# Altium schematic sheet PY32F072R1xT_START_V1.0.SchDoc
size 381 x 254 mm; SheetNumber: 1; SheetTotal: 1
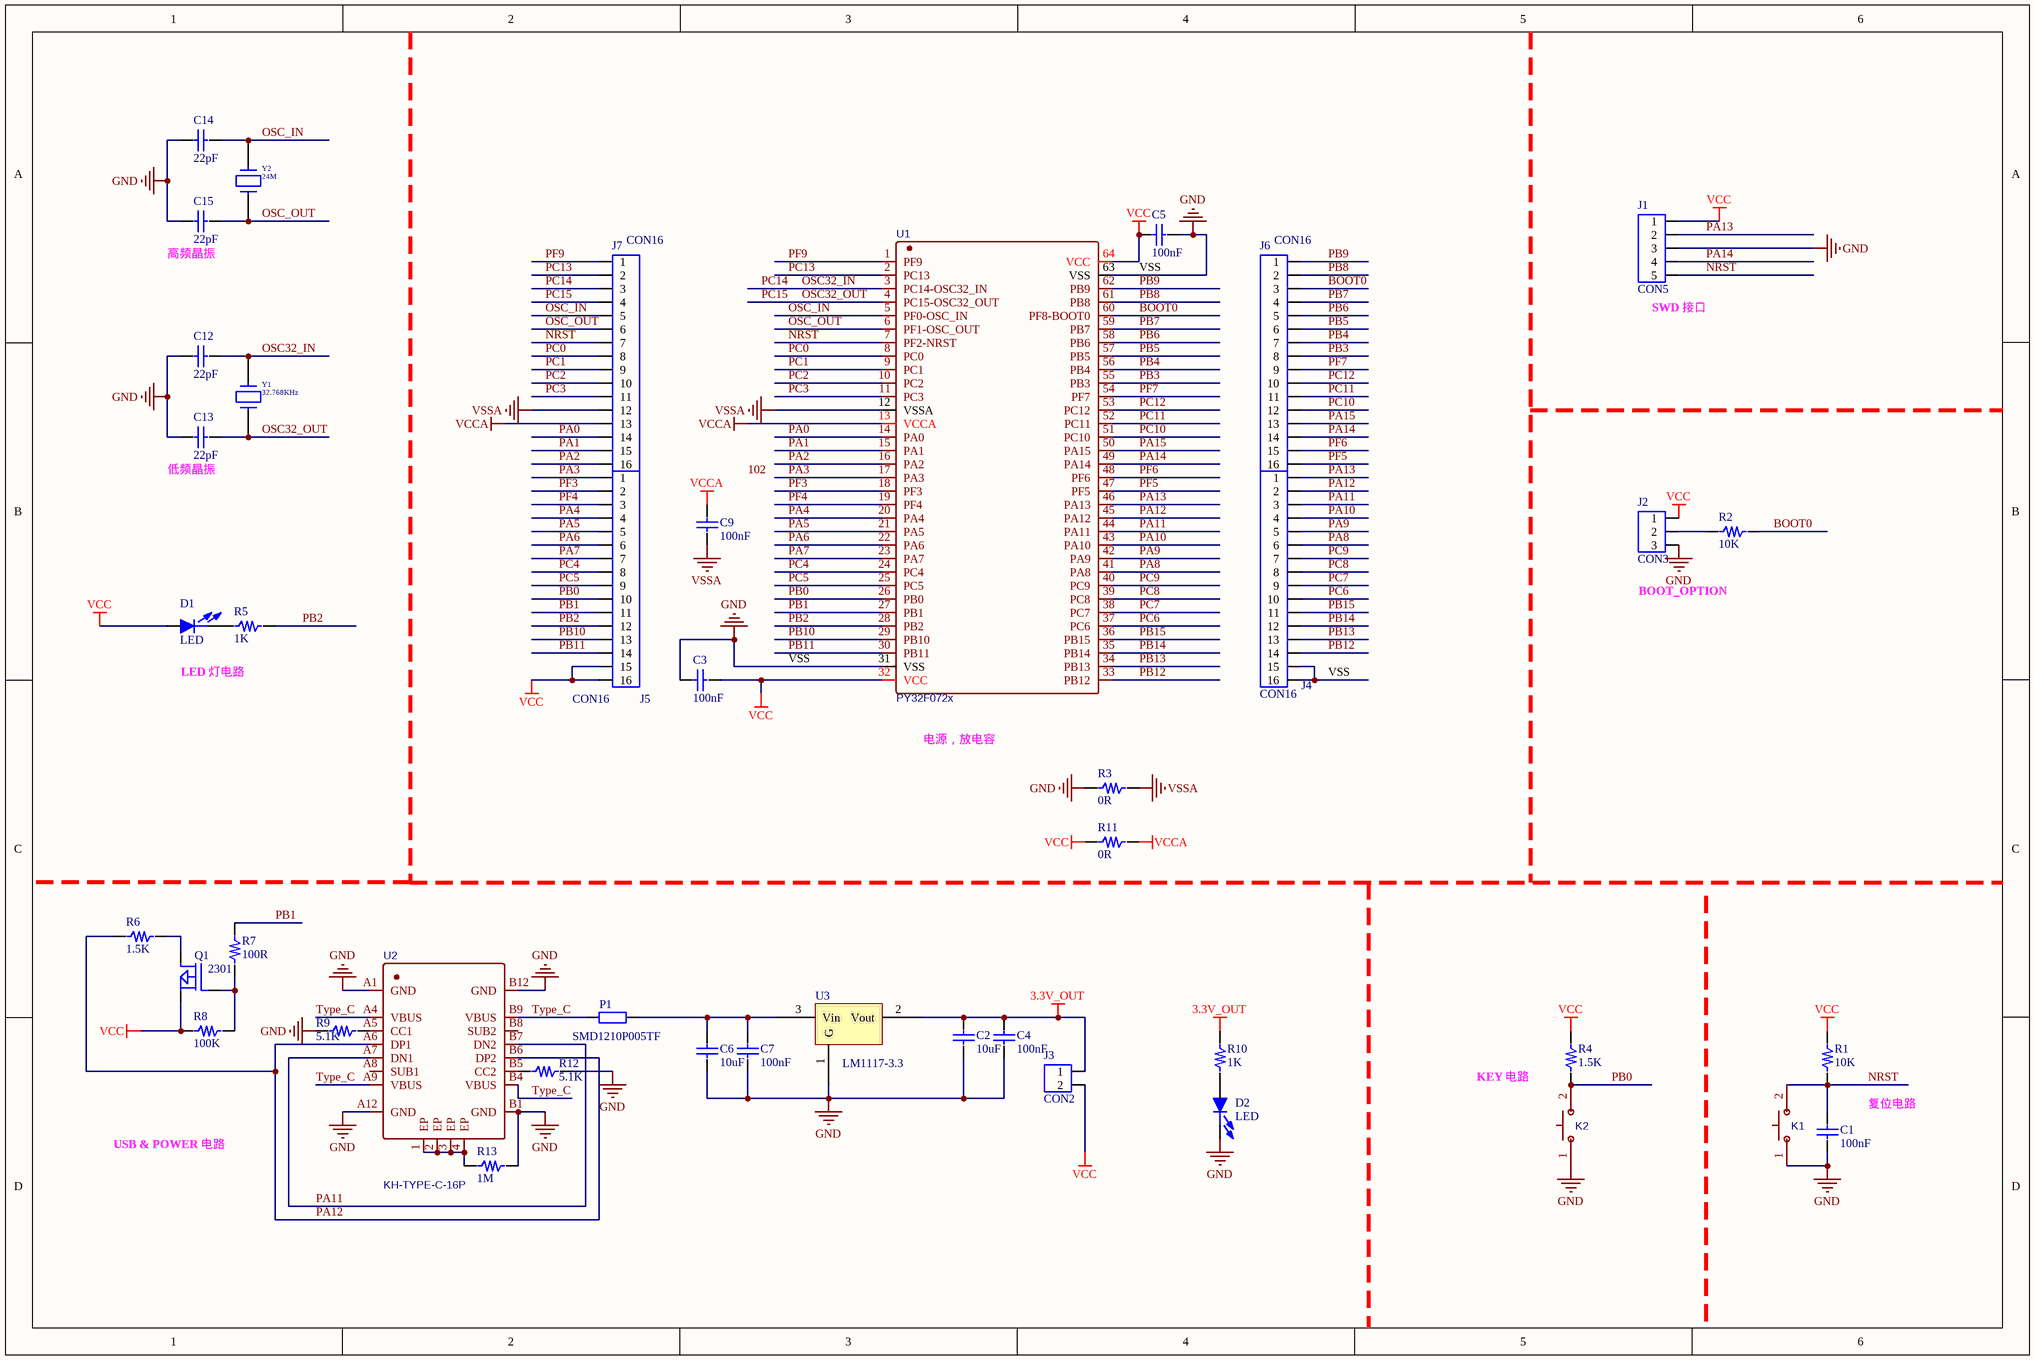
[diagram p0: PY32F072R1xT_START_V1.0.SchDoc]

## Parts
C1  100nF  [C0603]
C2  10uF  [C0805]
C3  100nF  [C0603]
C4  100nF  [C0603]
C5  100nF  [C0603]
C6  10uF  [C0805]
C7  100nF  [C0603]
C9  100nF  [C0603]
C12  22pF  [C0603]
C13  22pF  [C0603]
C14  22pF  [C0603]
C15  22pF  [C0603]
D1  LED  [LED-0805]
D2  LED  [LED-0805]
J1  CON5  [CON5]
J2  CON3  [CON3]
J3  CON2  [CON2]
J4  CON16  [CON16]
J5  CON16  [CON16]
J6  CON16  [CON16]
J7  CON16  [CON16]
K1  1TS002B-2600-5001_key  [SW]  (value not drawn)
K2  1TS002B-2600-5001_key  [SW]  (value not drawn)
P1  SMD1210P005TF  [SDM1210P005TF]
Q1  2301  [SOT23 2301]
R1  10K  [R0603]
R2  10K  [R0603]
R3  0R  [R0603]
R4  1.5K  [R0603]
R5  1K  [R0603]
R6  1.5K  [R0603]
R7  100R  [R0603]
R8  100K  [R0603]
R9  5.1K  [R0603]
R10  1K  [R0603]
R11  0R  [R0603]
R12  5.1K  [R0603]
R13  1M  [R0603]
U1  PY32F072x  [LQFP-64_L10.0-W10.0-P0.50-LS12.0-BL]
U2  KH-TYPE-C-16P  [USB-C-SMD_KH-TYPE-C-16P]
U3  LM1117-3.3  [LM1117-3.3]
Y1  32.768KHz  [32768KHZ_2]
Y2  24M  [25MHZ_2]

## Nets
3.3V_OUT: C2.2 C4.2 J3.1 R10.2 U3.2(Vout)
VCC: C3.2 C5.2 D1.2 J1.1 J2.1 J3.2 J5.15 J5.16 Q1.2(S) R1.2 R4.2 R8.1 R11.1 U1.32(VCC) U1.64(VCC)
VCCA: C9.2 J7.13 R11.2 U1.13(VCCA)
VSS: C1.1 C2.1 C3.1 C4.1 C5.1 C6.1 C7.1 C12.2 C13.2 C14.2 C15.2 D2.1 J1.3 J2.3 J4.15 J4.16 K1.1(A) K2.1(A) R3.1 R9.2 R12.1 R13.1 U1.31(VSS) U1.63(VSS) U2.A1(GND) U2.A12(GND) U2.B1(GND) U2.B12(GND) U3.1(G)  [also labelled GND]
VSSA: C9.1 J7.12 R3.2 U1.12(VSSA)
BOOT0: J6.3 R2.2 U1.60(PF8-BOOT0)
NRST: C1.2 J1.5 J7.7 K1.2(B) R1.1 U1.7(PF2-NRST)
OSC32_IN: C12.1 J7.3 U1.3(PC14-OSC32_IN) Y1.1  [also labelled PC14]
OSC32_OUT: C13.1 J7.4 U1.4(PC15-OSC32_OUT) Y1.2  [also labelled PC15]
OSC_IN: C14.1 J7.5 U1.5(PF0-OSC_IN) Y2.2
OSC_OUT: C15.1 J7.6 U1.6(PF1-OSC_OUT) Y2.1
PA0: J7.14 U1.14(PA0)
PA1: J7.15 U1.15(PA1)
PA2: J7.16 U1.16(PA2)
PA3: J5.1 U1.17(PA3)
PA4: J5.4 U1.20(PA4)
PA5: J5.5 U1.21(PA5)
PA6: J5.6 U1.22(PA6)
PA7: J5.7 U1.23(PA7)
PA8: J4.6 U1.41(PA8)
PA9: J4.5 U1.42(PA9)
PA10: J4.4 U1.43(PA10)
PA11: J4.3 U1.44(PA11) U2.A7(DN1) U2.B7(DN2)
PA12: J4.2 R6.1 U1.45(PA12) U2.A6(DP1) U2.B6(DP2)
PA13: J1.2 J4.1 U1.46(PA13)
PA14: J1.4 J6.14 U1.49(PA14)
PA15: J6.13 U1.50(PA15)
PB0: J5.10 K2.2(B) R4.1 U1.26(PB0)
PB1: J5.11 R7.2 U1.27(PB1)
PB2: J5.12 R5.2 U1.28(PB2)
PB3: J6.8 U1.55(PB3)
PB4: J6.7 U1.56(PB4)
PB5: J6.6 U1.57(PB5)
PB6: J6.5 U1.58(PB6)
PB7: J6.4 U1.59(PB7)
PB8: J6.2 U1.61(PB8)
PB9: J6.1 U1.62(PB9)
PB10: J5.13 U1.29(PB10)
PB11: J5.14 U1.30(PB11)
PB12: J4.14 U1.33(PB12)
PB13: J4.13 U1.34(PB13)
PB14: J4.12 U1.35(PB14)
PB15: J4.11 U1.36(PB15)
PC0: J7.8 U1.8(PC0)
PC1: J7.9 U1.9(PC1)
PC2: J7.10 U1.10(PC2)
PC3: J7.11 U1.11(PC3)
PC4: J5.8 U1.24(PC4)
PC5: J5.9 U1.25(PC5)
PC6: J4.10 U1.37(PC6)
PC7: J4.9 U1.38(PC7)
PC8: J4.8 U1.39(PC8)
PC9: J4.7 U1.40(PC9)
PC10: J6.12 U1.51(PC10)
PC11: J6.11 U1.52(PC11)
PC12: J6.10 U1.53(PC12)
PC13: J7.2 U1.2(PC13)
PF3: J5.2 U1.18(PF3)
PF4: J5.3 U1.19(PF4)
PF5: J6.16 U1.47(PF5)
PF6: J6.15 U1.48(PF6)
PF7: J6.9 U1.54(PF7)
PF9: J7.1 U1.1(PF9)
Type_C: P1.1 U2.A4(VBUS) U2.A9(VBUS) U2.B4(VBUS) U2.B9(VBUS)
NetC6_2: C6.2 C7.2 P1.2 U3.3(Vin)
NetD1_1: D1.1 R5.1
NetD2_2: D2.2 R10.1
NetJ2_2: J2.2 R2.1
NetQ1_1: Q1.1(G) R7.1 R8.2
NetQ1_3: Q1.3(D) R6.2
NetR9_1: R9.1 U2.A5(CC1)
NetR12_2: R12.2 U2.B5(CC2)
NetR13_2: R13.2 U2.1(EP) U2.2(EP) U2.3(EP) U2.4(EP)

Not connected (* = marked no-connect by the designer): U2 A8(SUB1) B8(SUB2)

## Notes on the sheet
- (near C15) 高频晶振
- (near J1) SWD 接口
- (near C13) 低频晶振
- BOOT_OPTION
- LED 灯电路
- 电源，放电容
- KEY 电路
- 复位电路
- USB & POWER 电路
- Labels drawn without touching a wire or pin: 102

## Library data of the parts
C1 C3-C5 C7 C9 C12-C15 = C0603: PCB DECAL: 0603
C2 C6 = C0805: PCB DECAL: 0805
D1 D2 = LED_0805: PCB DECAL: 0805
K1 K2 = 1TS002B-2600-5001_key: BOM_Manufacturer: HYP; Contributor: LCSC
Q1 = MOSFET P: Value: SI2301; 器件封装(外观): SOT23
R1-R13 = R0603: PCB DECAL: 0603
U1 = PY32F072x: BOM_Manufacturer: ST; BOM_Manufacturer Part: STM32F103VCT6; subpart_no: 2; tags: STM32
U2 = KH-TYPE-C-16P: BOM_Manufacturer: Shenzhen Kinghelm Elec; Contributor: LCSC
Y1 = CRYSTAL_1: Crystal; Value: X503225MSB2GI
Y2 = CRYSTAL: Value: X503225MSB2GI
